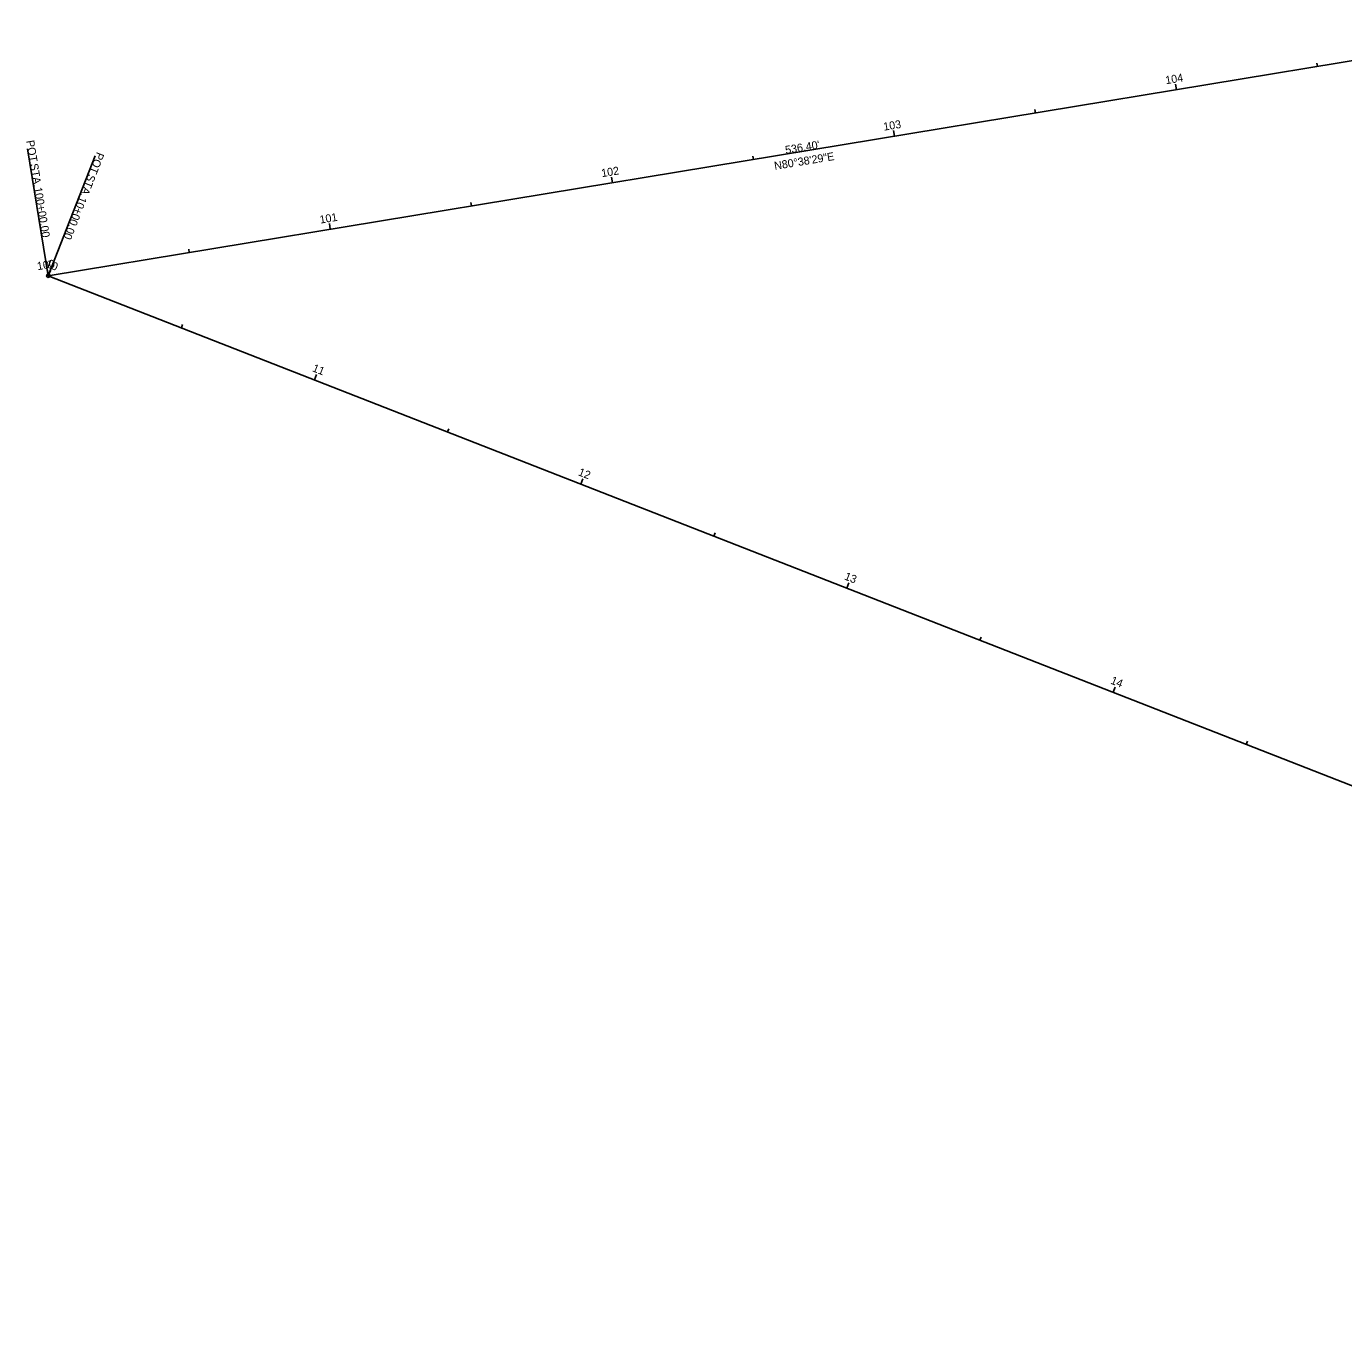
# Model space of a CAD drawing. Extents: x 1462082 to 1464344, y 432818 to 434093.
# Drawn here: x 1462081.7 to 1462542.6, y 433327.2 to 433780 of the extents above; entities that cross this region are included whole.
import ezdxf

# ---------------------------------------------------------------- set-up
doc = ezdxf.new("R2010")
doc.units = 0
for name, color, linetype in [('GE_P_Alignment', 7, 'Continuous'), ('GE_P_Alignment_100_Bearings', 7, 'Continuous'), ('GE_P_Alignment_100_Cardinal_Points', 7, 'Continuous'), ('GE_P_Alignment_100_Distances', 7, 'Continuous'), ('GE_P_Alignment_100_Stations', 7, 'Continuous')]:
    doc.layers.add(name, color=color, linetype=linetype)

msp = doc.modelspace()

# ---------------------------------------------------------------- linework, layer by layer
at = {"layer": 'GE_P_Alignment'}
for q in [(1462618.63, 433779.96), (1464324.41, 432818.38)]:
    msp.add_line((1462089.36, 433692.74), q, dxfattribs=at)
at = {"layer": 'GE_P_Alignment_100_Cardinal_Points'}
for q in [(1462082.05, 433737.14), (1462105.76, 433734.64)]:
    msp.add_line((1462089.36, 433692.74), q, dxfattribs=at)
msp.add_circle((1462089.36, 433692.74), 0.6, dxfattribs=at)
msp.add_circle((1462089.36, 433692.74), 0.6, dxfattribs=at)
at = {"layer": 'GE_P_Alignment_100_Stations'}
for p, q in [((1462533.37, 433765.91), (1462533.18, 433767.09)), ((1462484.04, 433757.78), (1462483.71, 433759.75)), ((1462434.7, 433749.65), (1462434.51, 433750.83)), ((1462385.37, 433741.52), (1462385.05, 433743.49)), ((1462336.04, 433733.39), (1462335.84, 433734.57)), ((1462286.7, 433725.26), (1462286.38, 433727.23)), ((1462237.37, 433717.13), (1462237.17, 433718.31)), ((1462188.03, 433709), (1462187.71, 433710.97)), ((1462138.7, 433700.87), (1462138.5, 433702.05)), ((1462089.36, 433692.74), (1462089.04, 433694.71)), ((1462089.36, 433692.74), (1462090.09, 433694.6)), ((1462135.93, 433674.52), (1462136.36, 433675.64)), ((1462182.49, 433656.3), (1462183.22, 433658.17)), ((1462229.05, 433638.09), (1462229.49, 433639.21)), ((1462275.62, 433619.87), (1462276.35, 433621.73)), ((1462322.18, 433601.66), (1462322.62, 433602.77)), ((1462368.75, 433583.44), (1462369.47, 433585.3)), ((1462415.31, 433565.22), (1462415.75, 433566.34)), ((1462461.87, 433547.01), (1462462.6, 433548.87)), ((1462508.44, 433528.79), (1462508.87, 433529.91))]:
    msp.add_line(p, q, dxfattribs=at)

# ---------------------------------------------------------------- texts
at = {"layer": 'GE_P_Alignment_100_Bearings'}
msp.add_text('N80°38\'29"E', height=2.8, rotation=9.3585, dxfattribs=at).set_placement((1462343.56, 433729.76))
at = {"layer": 'GE_P_Alignment_100_Cardinal_Points'}
for s, rotation, p in [('POT', 279.3585, (1462081.63, 433739.91)), ('POT', 248.6344, (1462106.41, 433736.19)), (' STA. ', 279.3585, (1462082.8, 433732.8)), (' STA. ', 248.6344, (1462103.79, 433729.49)), ('100+00.00', 279.3585, (1462084.34, 433723.47)), ('10+00.00', 248.6344, (1462100.34, 433720.69))]:
    msp.add_text(s, height=2.8, rotation=rotation, dxfattribs=at).set_placement(p)
at = {"layer": 'GE_P_Alignment_100_Distances'}
msp.add_text("536.40'", height=2.8, rotation=9.3585, dxfattribs=at).set_placement((1462347.4, 433735.3))
at = {"layer": 'GE_P_Alignment_100_Stations'}
for s, rotation, p in [('104', 9.3585, (1462480.4, 433759.71)), ('103', 9.3585, (1462381.74, 433743.45)), ('102', 9.3585, (1462283.06, 433727.19)), ('101', 9.3585, (1462184.52, 433710.95)), ('100', 9.3585, (1462085.65, 433694.66)), ('10', 338.6344, (1462088.2, 433695.88)), ('11', 338.6344, (1462181.51, 433659.37)), ('12', 338.6344, (1462274.52, 433622.99)), ('13', 338.6344, (1462367.65, 433586.55)), ('14', 338.6344, (1462460.78, 433550.12))]:
    msp.add_text(s, height=2.8, rotation=rotation, dxfattribs=at).set_placement(p)

doc.saveas('drawing.dxf')
